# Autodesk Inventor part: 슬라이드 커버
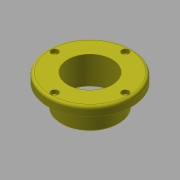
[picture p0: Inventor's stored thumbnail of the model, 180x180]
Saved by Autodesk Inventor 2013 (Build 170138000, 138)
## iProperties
Created: 2015-10
Part Number: 슬라이드 커버
Document SubType Name: Modeling
Designer: mdu
Density: 7.86 g/cm^3
Material: 강철, 연강
Mass: 598.523 g
Surface Area: 229.996 cm^2
Volume: 76.148 cm^3
Author: mdu
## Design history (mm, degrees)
sketch "스케치1"
  geometry: C1 r 47.5 at (0, 0); C2 r 32.5 at (0, 0); 1 further point
  constraints: 2 centre point, 2 coincident
  dimensions: "d33" = 95 diameter of C1; "d35" = 65 diameter of C2
extrude "돌출1" new body sketch "스케치1" distance "d0" = 10; taper "d1" = 0 deg
extrude "돌출2" join sketch "스케치1" distance "d2" = 25; taper "d3" = 0 deg
hole "구멍1" diameter "d6" = 50; stored, may be unused: countersink angle "d10" = 90 deg, drill point angle "d12" = 118 deg; dims "d4" = 10, "d5" = 10, "d7" = 6, "d8" = 4, "d9" = 2, "d11" = 8
sketch "스케치2" dims "d36" = 80
  geometry: 4 further points
  constraints: 2 coincident, 2 vertical alignment, 2 other
hole "구멍2" sketch "스케치2" at (0, 40) diameter "d13" = 4.5; stored, may be unused: countersink angle "d17" = 90 deg, drill point angle "d19" = 118 deg; dims "d14" = 6, "d15" = 8, "d16" = 4.4, "d18" = 8
fillet "모깎기1" dims "d23" = 3
chamfer "모따기1" distance "d24" = 1; stored, may be unused: second distance "d25" = 2, angle "d26" = 45 deg
sketch "스케치3"
  geometry: C1 r 25 at (0, 0); C2 r 30 at (0, 0); C3 r 26 at (0, 0) reference; 1 further point
  constraints: 2 centre point, 2 coincident
  dimensions: "d27" = 60 diameter of C2
extrude "돌출3" cut sketch "스케치3" distance "d28" = 3; taper "d29" = 0 deg
chamfer "모따기2" distance "d30" = 1; stored, may be unused: second distance "d31" = 2, angle "d32" = 45 deg
node "솔리드1"
pattern_circular "원형 패턴1" dims angle "d21" = 360 deg
